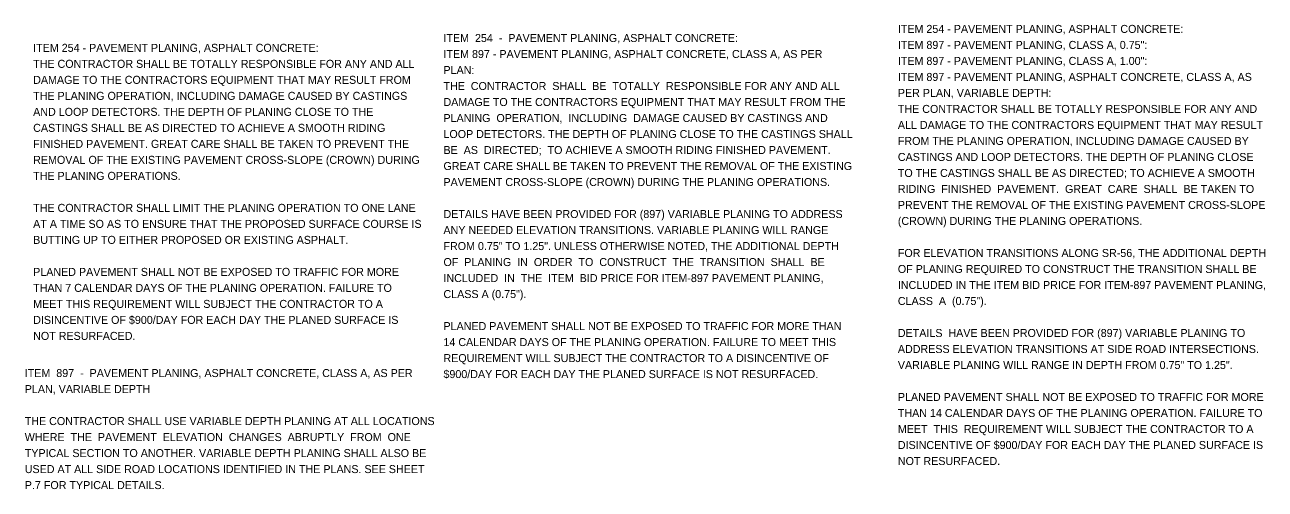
# Model space of a CAD drawing. Extents: x -22.4 to 62.7, y 0 to 22.4.
# Drawn here: x -22.4 to -0.71, y 0.99 to 9.11 of the extents above; entities that cross this region are included whole.
import ezdxf

# ---------------------------------------------------------------- set-up
doc = ezdxf.new("R2010")
doc.units = 0
doc.layers.add('Default', color=7, linetype='Continuous')
doc.layers.add('SH_Text', color=7, linetype='Continuous')

msp = doc.modelspace()

# ---------------------------------------------------------------- texts
at = {"layer": 'Default'}
for s, p in [('ITEM 254 - PAVEMENT PLANING, ASPHALT CONCRETE:', (-22.25, 8.639)), ('THE CONTRACTOR SHALL BE TOTALLY RESPONSIBLE FOR ANY AND ALL ', (-22.25, 8.359)), ('DAMAGE TO THE CONTRACTORS EQUIPMENT THAT MAY RESULT FROM ', (-22.25, 8.079)), ('THE PLANING OPERATION, INCLUDING DAMAGE CAUSED BY CASTINGS', (-22.25, 7.799)), ('AND LOOP DETECTORS. THE DEPTH OF PLANING CLOSE TO THE ', (-22.25, 7.519)), ('CASTINGS SHALL BE AS DIRECTED TO ACHIEVE A SMOOTH RIDING ', (-22.25, 7.239)), ('FINISHED PAVEMENT. GREAT CARE SHALL BE TAKEN TO PREVENT THE ', (-22.25, 6.959)), ('REMOVAL OF THE EXISTING PAVEMENT CROSS-SLOPE (CROWN) DURING ', (-22.25, 6.679)), ('THE PLANING OPERATIONS.', (-22.25, 6.399)), ('THE CONTRACTOR SHALL LIMIT THE PLANING OPERATION TO ONE LANE ', (-22.25, 5.839)), ('AT A TIME SO AS TO ENSURE THAT THE PROPOSED SURFACE COURSE IS ', (-22.25, 5.559)), ('BUTTING UP TO EITHER PROPOSED OR EXISTING ASPHALT.', (-22.25, 5.279)), ('PLANED PAVEMENT SHALL NOT BE EXPOSED TO TRAFFIC FOR MORE ', (-22.25, 4.719)), ('THAN 7 CALENDAR DAYS OF THE PLANING OPERATION. FAILURE TO ', (-22.25, 4.439)), ('MEET THIS REQUIREMENT WILL SUBJECT THE CONTRACTOR TO A ', (-22.25, 4.159)), ('DISINCENTIVE OF $900/DAY FOR EACH DAY THE PLANED SURFACE IS ', (-22.25, 3.879)), ('NOT RESURFACED.', (-22.25, 3.599))]:
    msp.add_text(s, height=0.14, dxfattribs=at).set_placement(p)
at = {"layer": 'SH_Text'}
for s, p in [('ITEM 254 - PAVEMENT PLANING, ASPHALT CONCRETE:', (-7.129, 8.97)), ('ITEM  254  -  PAVEMENT PLANING, ASPHALT CONCRETE:', (-15.075, 8.811)), ('ITEM 897 - PAVEMENT PLANING, CLASS A, 0.75":', (-7.129, 8.69)), ('ITEM 897 - PAVEMENT PLANING, ASPHALT CONCRETE, CLASS A, AS PER', (-15.075, 8.531)), ('ITEM 897 - PAVEMENT PLANING, CLASS A, 1.00":', (-7.129, 8.41)), ('PLAN:', (-15.075, 8.251)), ('ITEM 897 - PAVEMENT PLANING, ASPHALT CONCRETE, CLASS A, AS', (-7.129, 8.13)), ('THE  CONTRACTOR  SHALL  BE  TOTALLY  RESPONSIBLE FOR ANY AND ALL', (-15.075, 7.971)), ('DAMAGE TO THE CONTRACTORS EQUIPMENT THAT MAY RESULT FROM THE', (-15.075, 7.691)), ('PER PLAN, VARIABLE DEPTH:', (-7.129, 7.85)), ('THE CONTRACTOR SHALL BE TOTALLY RESPONSIBLE FOR ANY AND', (-7.129, 7.57)), ('PLANING  OPERATION,  INCLUDING  DAMAGE CAUSED BY CASTINGS AND', (-15.075, 7.411)), ('ALL DAMAGE TO THE CONTRACTORS EQUIPMENT THAT MAY RESULT', (-7.129, 7.29)), ('LOOP DETECTORS. THE DEPTH OF PLANING CLOSE TO THE CASTINGS SHALL', (-15.075, 7.131)), ('BE  AS  DIRECTED;  TO ACHIEVE A SMOOTH RIDING FINISHED PAVEMENT.', (-15.075, 6.851)), ('FROM THE PLANING OPERATION, INCLUDING DAMAGE CAUSED BY', (-7.129, 7.01)), ('CASTINGS AND LOOP DETECTORS. THE DEPTH OF PLANING CLOSE', (-7.129, 6.73)), ('GREAT CARE SHALL BE TAKEN TO PREVENT THE REMOVAL OF THE EXISTING', (-15.075, 6.571)), ('TO THE CASTINGS SHALL BE AS DIRECTED; TO ACHIEVE A SMOOTH', (-7.129, 6.45)), ('PAVEMENT CROSS-SLOPE (CROWN) DURING THE PLANING OPERATIONS.', (-15.075, 6.291)), ('RIDING  FINISHED  PAVEMENT.  GREAT  CARE  SHALL  BE TAKEN TO', (-7.129, 6.17)), ('DETAILS HAVE BEEN PROVIDED FOR (897) VARIABLE PLANING TO ADDRESS', (-15.075, 5.731)), ('PREVENT THE REMOVAL OF THE EXISTING PAVEMENT CROSS-SLOPE', (-7.129, 5.89)), ('(CROWN) DURING THE PLANING OPERATIONS.', (-7.129, 5.61)), ('ANY NEEDED ELEVATION TRANSITIONS. VARIABLE PLANING WILL RANGE', (-15.075, 5.451)), ('FROM 0.75" TO 1.25". UNLESS OTHERWISE NOTED, THE ADDITIONAL DEPTH', (-15.075, 5.171)), ('OF  PLANING  IN  ORDER  TO  CONSTRUCT  THE  TRANSITION  SHALL  BE', (-15.075, 4.891)), ('FOR ELEVATION TRANSITIONS ALONG SR-56, THE ADDITIONAL DEPTH', (-7.129, 5.05)), ('OF PLANING REQUIRED TO CONSTRUCT THE TRANSITION SHALL BE', (-7.129, 4.77)), ('INCLUDED  IN  THE  ITEM  BID PRICE FOR ITEM-897 PAVEMENT PLANING,', (-15.075, 4.611)), ('INCLUDED IN THE ITEM BID PRICE FOR ITEM-897 PAVEMENT PLANING,', (-7.129, 4.49)), ('CLASS A (0.75").', (-15.075, 4.331)), ('CLASS  A  (0.75").', (-7.129, 4.21)), ('PLANED PAVEMENT SHALL NOT BE EXPOSED TO TRAFFIC FOR MORE THAN', (-15.075, 3.771)), ('DETAILS  HAVE BEEN PROVIDED FOR (897) VARIABLE PLANING TO', (-7.129, 3.65)), ('14 CALENDAR DAYS OF THE PLANING OPERATION. FAILURE TO MEET THIS', (-15.075, 3.491)), ('ADDRESS ELEVATION TRANSITIONS AT SIDE ROAD INTERSECTIONS.', (-7.129, 3.37)), ('REQUIREMENT WILL SUBJECT THE CONTRACTOR TO A DISINCENTIVE OF', (-15.075, 3.211)), ('ITEM  897  -  PAVEMENT PLANING, ASPHALT CONCRETE, CLASS A, AS PER', (-22.397, 2.949)), ('$900/DAY FOR EACH DAY THE PLANED SURFACE IS NOT RESURFACED.', (-15.075, 2.931)), ('VARIABLE PLANING WILL RANGE IN DEPTH FROM 0.75" TO 1.25".', (-7.129, 3.09)), ('PLAN, VARIABLE DEPTH', (-22.397, 2.669)), ('PLANED PAVEMENT SHALL NOT BE EXPOSED TO TRAFFIC FOR MORE', (-7.129, 2.53)), ('THAN 14 CALENDAR DAYS OF THE PLANING OPERATION. FAILURE TO', (-7.129, 2.25)), ('THE CONTRACTOR SHALL USE VARIABLE DEPTH PLANING AT ALL LOCATIONS', (-22.397, 2.109)), ('WHERE  THE  PAVEMENT  ELEVATION  CHANGES  ABRUPTLY  FROM  ONE', (-22.397, 1.829)), ('MEET  THIS  REQUIREMENT WILL SUBJECT THE CONTRACTOR TO A', (-7.129, 1.97)), ('DISINCENTIVE OF $900/DAY FOR EACH DAY THE PLANED SURFACE IS', (-7.129, 1.69)), ('TYPICAL SECTION TO ANOTHER. VARIABLE DEPTH PLANING SHALL ALSO BE', (-22.397, 1.549)), ('NOT RESURFACED.', (-7.129, 1.41)), ('USED AT ALL SIDE ROAD LOCATIONS IDENTIFIED IN THE PLANS. SEE SHEET', (-22.397, 1.269)), ('P.7', (-22.397, 0.989)), (' FOR TYPICAL DETAILS.', (-22.115, 0.989))]:
    msp.add_text(s, height=0.14, dxfattribs=at).set_placement(p)

doc.saveas('drawing.dxf')
